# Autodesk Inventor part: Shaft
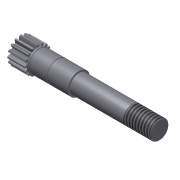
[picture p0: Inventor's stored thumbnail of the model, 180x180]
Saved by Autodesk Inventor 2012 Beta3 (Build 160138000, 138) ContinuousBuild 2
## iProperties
Created: 2010-12
Part Number: Shaft
Material: Steel
Document SubType Name: Modeling
Designer: Thom Tremblay
Density: 1 g/cm^3
CustomPartVersion: 0
Author: Thom Tremblay
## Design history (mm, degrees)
sketch "Main Sketch"
  geometry: L1 (0, 0)-(95, 0) reference; L2 (0, 0)-(0, 12.5); L3 (12, 12.5)-(12, 7.5); L4 (0, 12.5)-(12, 12.5); L5 (40, 7.5)-(40, 6.5); L6 (12, 7.5)-(40, 7.5); L7 (95, 6.5)-(95, 0); L8 (40, 6.5)-(95, 6.5)
  constraints: 16 end point, 4 vertical, 2 horizontal
  dimensions: "d3" = 25 diameter of L4 L1 (derived); "d5" = 15 diameter of L6 L1 (derived); "d13" = 13 diameter of L8 L1 (derived)
revolve "Revolution1" sketch "Main Sketch" stored, may be unused: angle "d6" = 0 deg
chamfer "Chamfer3" distance "d14" = 0.5; stored, may be unused: second distance "d15" = 0.125, angle "d16" = 45 deg
node "Retaining Ring Groove2"
node "Retaining Ring Groove1"
chamfer "Chamfer1" distance "d7" = 0.5; stored, may be unused: second distance "d8" = 0.125, angle "d9" = 45 deg
node "Spur Gear Teeth1"
thread "Thread1" dims "d17" = 18, "d18" = 0
body "Solid1"
feature "iFeature27:1"
feature "iFeature27:2"
feature "Spur Gear1"
other parameters: "d0" = 0, "d1" = 0, "d2" = 0
